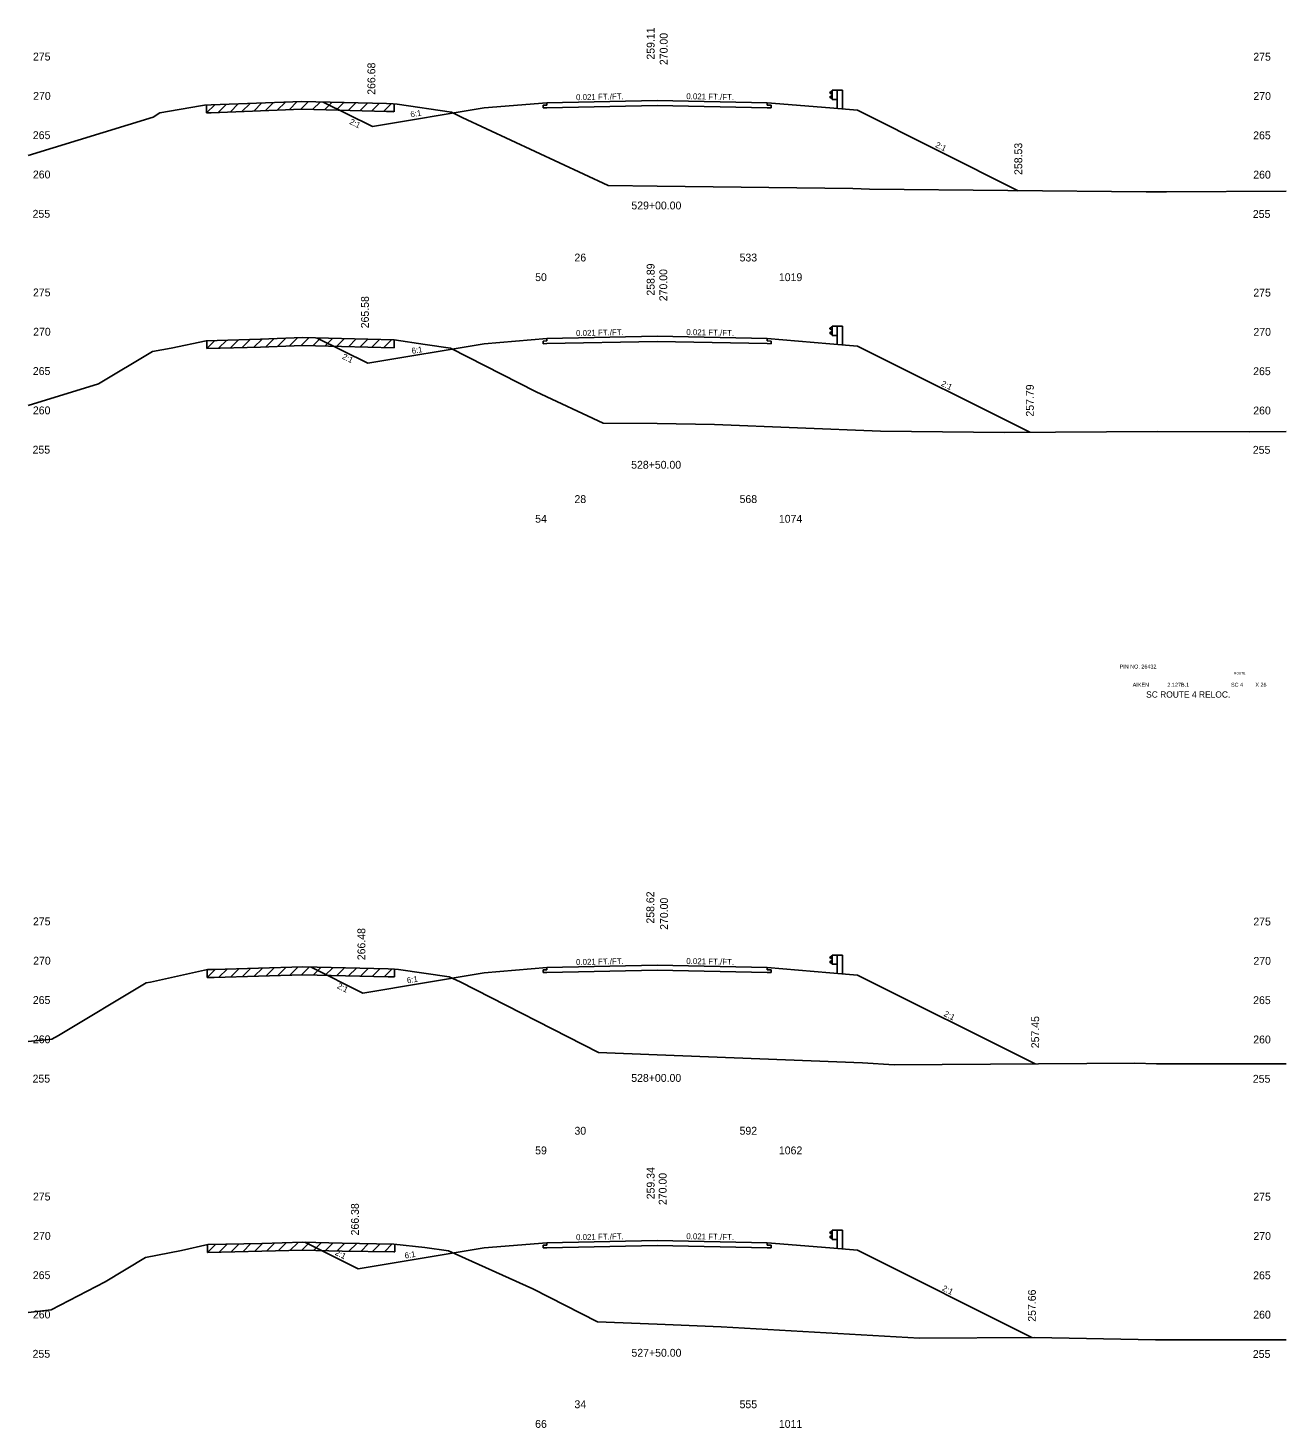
# Model space of a CAD drawing. Extents: x 2967 to 4323, y -3677 to -817.
# Drawn here: x 3555.3 to 3715.3, y -3673.7 to -3495.6 of the extents above; entities that cross this region are included whole.
import ezdxf

# ---------------------------------------------------------------- set-up
doc = ezdxf.new("R2010")
doc.units = 0
for name, color, linetype in [('Level 1', 7, 'Continuous'), ('Level 10', 7, 'Continuous'), ('Level 11', 7, 'Continuous'), ('Level 12', 7, 'Continuous'), ('Level 20', 7, 'Continuous'), ('Level 24', 7, 'Continuous'), ('Level 3', 7, 'Continuous'), ('Level 32', 7, 'Continuous'), ('Level 33', 7, 'Continuous'), ('Level 59', 7, 'Continuous'), ('Level 6', 7, 'Continuous'), ('Level 60', 7, 'Continuous'), ('Level 61', 7, 'Continuous'), ('Level 7', 7, 'Continuous')]:
    doc.layers.add(name, color=color, linetype=linetype)

msp = doc.modelspace()

# ---------------------------------------------------------------- linework, layer by layer
at = {"layer": 'Level 11'}
for p, q in [((3621.35, -3505.43), (3620.85, -3505.44)), ((3620.85, -3505.44), (3620.85, -3505.78)), ((3620.85, -3505.78), (3621.35, -3505.77)), ((3621.35, -3505.13), (3621.35, -3505.43)), ((3649.35, -3505.43), (3649.35, -3505.13)), ((3649.85, -3505.44), (3649.35, -3505.43)), ((3649.35, -3505.77), (3649.85, -3505.78)), ((3649.85, -3505.78), (3649.85, -3505.44)), ((3621.35, -3535.43), (3620.85, -3535.44)), ((3620.85, -3535.44), (3620.85, -3535.78)), ((3620.85, -3535.78), (3621.35, -3535.77)), ((3621.35, -3535.13), (3621.35, -3535.43)), ((3649.35, -3535.43), (3649.35, -3535.13)), ((3649.85, -3535.44), (3649.35, -3535.43)), ((3649.35, -3535.77), (3649.85, -3535.78)), ((3649.85, -3535.78), (3649.85, -3535.44)), ((3621.35, -3615.43), (3620.85, -3615.44)), ((3620.85, -3615.44), (3620.85, -3615.78)), ((3620.85, -3615.78), (3621.35, -3615.77)), ((3621.35, -3615.13), (3621.35, -3615.43)), ((3649.35, -3615.43), (3649.35, -3615.13)), ((3649.85, -3615.44), (3649.35, -3615.43)), ((3649.35, -3615.77), (3649.85, -3615.78)), ((3649.85, -3615.78), (3649.85, -3615.44)), ((3621.35, -3650.43), (3620.85, -3650.44)), ((3620.85, -3650.44), (3620.85, -3650.78)), ((3621.35, -3650.13), (3621.35, -3650.43)), ((3649.35, -3650.43), (3649.35, -3650.13)), ((3649.85, -3650.44), (3649.35, -3650.43)), ((3649.85, -3650.78), (3649.85, -3650.44)), ((3620.85, -3650.78), (3621.35, -3650.77)), ((3649.35, -3650.77), (3649.85, -3650.78))]:
    msp.add_line(p, q, dxfattribs=at)
at = {"layer": 'Level 12'}
for p, q in [((3635.35, -3505.48), (3621.35, -3505.77)), ((3649.35, -3505.77), (3635.35, -3505.48)), ((3635.35, -3535.48), (3621.35, -3535.77)), ((3649.35, -3535.77), (3635.35, -3535.48)), ((3635.35, -3615.48), (3621.35, -3615.77)), ((3649.35, -3615.77), (3635.35, -3615.48)), ((3635.35, -3650.48), (3621.35, -3650.77)), ((3649.35, -3650.77), (3635.35, -3650.48))]:
    msp.add_line(p, q, dxfattribs=at)
at = {"layer": 'Level 24'}
for p, q in [((3657.62, -3503.62), (3657.35, -3503.82)), ((3657.35, -3503.82), (3657.35, -3503.87)), ((3657.35, -3503.87), (3657.62, -3504.07)), ((3657.35, -3504.39), (3657.62, -3504.19)), ((3657.35, -3504.44), (3657.35, -3504.39)), ((3657.62, -3504.64), (3657.35, -3504.44)), ((3657.62, -3504.72), (3657.62, -3503.55)), ((3657.62, -3503.55), (3658.28, -3503.55)), ((3658.28, -3503.55), (3658.28, -3505.88)), ((3658.28, -3503.55), (3658.95, -3503.55)), ((3658.95, -3503.55), (3658.95, -3505.93)), ((3657.62, -3504.72), (3658.29, -3504.72)), ((3657.62, -3533.62), (3657.35, -3533.82)), ((3657.35, -3533.82), (3657.35, -3533.87)), ((3657.35, -3533.87), (3657.62, -3534.07)), ((3657.35, -3534.39), (3657.62, -3534.19)), ((3657.35, -3534.44), (3657.35, -3534.39)), ((3657.62, -3534.64), (3657.35, -3534.44)), ((3657.62, -3534.72), (3657.62, -3533.55)), ((3657.62, -3533.55), (3658.28, -3533.55)), ((3657.62, -3534.72), (3658.29, -3534.72)), ((3658.28, -3533.55), (3658.28, -3535.88)), ((3658.28, -3533.55), (3658.95, -3533.55)), ((3658.95, -3533.55), (3658.95, -3535.93)), ((3657.62, -3613.62), (3657.35, -3613.82)), ((3657.35, -3613.82), (3657.35, -3613.87)), ((3657.35, -3613.87), (3657.62, -3614.07)), ((3657.35, -3614.39), (3657.62, -3614.19)), ((3657.35, -3614.44), (3657.35, -3614.39)), ((3657.62, -3614.64), (3657.35, -3614.44)), ((3657.62, -3614.72), (3657.62, -3613.55)), ((3657.62, -3613.55), (3658.28, -3613.55)), ((3657.62, -3614.72), (3658.29, -3614.72)), ((3658.28, -3613.55), (3658.28, -3615.88)), ((3658.28, -3613.55), (3658.95, -3613.55)), ((3658.95, -3613.55), (3658.95, -3615.93)), ((3657.62, -3648.62), (3657.35, -3648.82)), ((3657.62, -3649.72), (3657.62, -3648.55)), ((3657.62, -3648.55), (3658.28, -3648.55)), ((3658.28, -3648.55), (3658.28, -3650.88)), ((3658.28, -3648.55), (3658.95, -3648.55)), ((3658.95, -3648.55), (3658.95, -3650.93)), ((3657.35, -3648.82), (3657.35, -3648.87)), ((3657.35, -3648.87), (3657.62, -3649.07)), ((3657.35, -3649.39), (3657.62, -3649.19)), ((3657.35, -3649.44), (3657.35, -3649.39)), ((3657.62, -3649.64), (3657.35, -3649.44)), ((3657.62, -3649.72), (3658.29, -3649.72))]:
    msp.add_line(p, q, dxfattribs=at)
at = {"layer": 'Level 59'}
for p, q in [((3621.35, -3505.13), (3635.35, -3504.84)), ((3635.35, -3504.84), (3649.35, -3505.13)), ((3621.35, -3535.13), (3635.35, -3534.84)), ((3635.35, -3534.84), (3649.35, -3535.13)), ((3621.35, -3615.13), (3635.35, -3614.84)), ((3635.35, -3614.84), (3649.35, -3615.13)), ((3621.35, -3650.13), (3635.35, -3649.84)), ((3635.35, -3649.84), (3649.35, -3650.13))]:
    msp.add_line(p, q, dxfattribs=at)
at = {"layer": 'Level 6'}
for p, q in [((3613.35, -3505.8), (3621.35, -3505.13)), ((3649.35, -3505.13), (3657.35, -3505.8)), ((3657.35, -3505.8), (3660.85, -3506.09)), ((3613.35, -3535.8), (3621.35, -3535.13)), ((3649.35, -3535.13), (3657.35, -3535.8)), ((3657.35, -3535.8), (3660.85, -3536.09)), ((3613.35, -3615.8), (3621.35, -3615.13)), ((3649.35, -3615.13), (3657.35, -3615.8)), ((3657.35, -3615.8), (3660.85, -3616.09)), ((3613.35, -3650.8), (3621.35, -3650.13)), ((3649.35, -3650.13), (3657.35, -3650.8)), ((3657.35, -3650.8), (3660.85, -3651.09))]:
    msp.add_line(p, q, dxfattribs=at)
at = {"layer": 'Level 60'}
for p, q in [((3572.12, -3506.43), (3577.27, -3505.54)), ((3577.27, -3505.54), (3577.81, -3505.42)), ((3577.81, -3505.42), (3578.65, -3505.4)), ((3578.65, -3505.4), (3590.18, -3504.97)), ((3590.18, -3504.97), (3600.96, -3505.24)), ((3600.96, -3505.24), (3601.8, -3505.26)), ((3601.8, -3505.26), (3602.29, -3505.33)), ((3602.29, -3505.33), (3609.22, -3506.33)), ((3555.35, -3511.83), (3571.25, -3506.95)), ((3571.25, -3506.95), (3572.12, -3506.43)), ((3609.22, -3506.33), (3610.55, -3507.02)), ((3610.55, -3507.02), (3629.14, -3515.66)), ((3629.14, -3515.66), (3635.35, -3515.73)), ((3635.35, -3515.73), (3660.27, -3516.03)), ((3660.27, -3516.03), (3662.37, -3516.12)), ((3662.37, -3516.12), (3697.56, -3516.48)), ((3697.56, -3516.48), (3699.19, -3516.48)), ((3699.19, -3516.48), (3700.17, -3516.48)), ((3700.17, -3516.48), (3715.35, -3516.4)), ((3571.18, -3536.79), (3573.56, -3536.37)), ((3573.56, -3536.37), (3578, -3535.41)), ((3578, -3535.41), (3584.91, -3535.21)), ((3584.91, -3535.21), (3590.24, -3535.01)), ((3590.24, -3535.01), (3595.21, -3535.14)), ((3595.21, -3535.14), (3601.9, -3535.3)), ((3601.9, -3535.3), (3605.88, -3535.88)), ((3605.88, -3535.88), (3609.07, -3536.34)), ((3609.07, -3536.34), (3620, -3541.92)), ((3564.32, -3540.9), (3571.18, -3536.79)), ((3555.35, -3543.66), (3564.32, -3540.9)), ((3620, -3541.92), (3628.48, -3545.87)), ((3628.48, -3545.87), (3635.35, -3545.95)), ((3635.35, -3545.95), (3642.68, -3546.04)), ((3642.68, -3546.04), (3663.77, -3546.9)), ((3663.77, -3546.9), (3679.53, -3547.07)), ((3679.53, -3547.07), (3699.02, -3546.96)), ((3699.02, -3546.96), (3710.73, -3546.97)), ((3710.73, -3546.97), (3715.35, -3546.94)), ((3570.94, -3616.97), (3578.17, -3615.4)), ((3578.17, -3615.4), (3579.02, -3615.38)), ((3579.02, -3615.38), (3590.29, -3615.05)), ((3590.29, -3615.05), (3601.16, -3615.31)), ((3601.16, -3615.31), (3601.97, -3615.33)), ((3601.97, -3615.33), (3602.46, -3615.38)), ((3602.46, -3615.38), (3608.93, -3616.32)), ((3608.93, -3616.32), (3610.3, -3616.94)), ((3559.22, -3623.77), (3570.37, -3617.08)), ((3570.37, -3617.08), (3570.94, -3616.97)), ((3610.3, -3616.94), (3627.91, -3625.92)), ((3558.37, -3624.22), (3559.22, -3623.77)), ((3555.35, -3624.54), (3558.37, -3624.22)), ((3627.91, -3625.92), (3635.35, -3626.22)), ((3635.35, -3626.22), (3661.5, -3627.27)), ((3661.5, -3627.27), (3665.51, -3627.5)), ((3665.51, -3627.5), (3696.13, -3627.31)), ((3696.13, -3627.31), (3698.86, -3627.36)), ((3698.86, -3627.36), (3715.35, -3627.37)), ((3574.88, -3651.1), (3578.23, -3650.37)), ((3578.23, -3650.37), (3585.09, -3650.22)), ((3585.09, -3650.22), (3590.28, -3650.07)), ((3590.28, -3650.07), (3595.3, -3650.19)), ((3595.3, -3650.19), (3601.86, -3650.3)), ((3601.86, -3650.3), (3605.82, -3650.75)), ((3565.15, -3655.09), (3570.31, -3651.99)), ((3570.31, -3651.99), (3574.88, -3651.1)), ((3605.82, -3650.75), (3608.82, -3651.18)), ((3608.82, -3651.18), (3619.57, -3656)), ((3558.31, -3658.68), (3565.15, -3655.09)), ((3619.57, -3656), (3627.8, -3660.2)), ((3555.35, -3659.01), (3558.31, -3658.68)), ((3627.8, -3660.2), (3635.35, -3660.5)), ((3635.35, -3660.5), (3643.5, -3660.83)), ((3643.5, -3660.83), (3668.74, -3662.27)), ((3668.74, -3662.27), (3683.34, -3662.18)), ((3683.34, -3662.18), (3698.75, -3662.47)), ((3698.75, -3662.47), (3707.37, -3662.47)), ((3707.37, -3662.47), (3715.35, -3662.47))]:
    msp.add_line(p, q, dxfattribs=at)
at = {"layer": 'Level 61'}
for p, q in [((3579.09, -3505.38), (3578.05, -3506.41)), ((3578.05, -3505.41), (3578.05, -3506.41)), ((3578.65, -3506.4), (3590.18, -3505.97)), ((3580.59, -3505.32), (3579.55, -3506.36)), ((3582.09, -3505.27), (3581.05, -3506.31)), ((3583.59, -3505.21), (3582.55, -3506.25)), ((3585.09, -3505.16), (3584.05, -3506.2)), ((3586.59, -3505.1), (3585.55, -3506.14)), ((3588.09, -3505.05), (3587.05, -3506.08)), ((3589.59, -3504.99), (3588.55, -3506.03)), ((3591.04, -3504.99), (3590.05, -3505.97)), ((3590.18, -3505.97), (3600.96, -3506.24)), ((3592.53, -3505.03), (3591.55, -3506)), ((3594.03, -3505.06), (3593.05, -3506.04)), ((3595.53, -3505.1), (3594.55, -3506.08)), ((3597.03, -3505.14), (3596.05, -3506.11)), ((3598.53, -3505.18), (3597.55, -3506.15)), ((3600.03, -3505.21), (3599.05, -3506.19)), ((3601.53, -3505.25), (3600.55, -3506.23)), ((3600.96, -3506.24), (3601.8, -3506.26)), ((3601.9, -3506.27), (3601.9, -3505.27)), ((3578.05, -3506.41), (3578.65, -3506.4)), ((3601.8, -3506.26), (3601.9, -3506.27)), ((3579.12, -3535.38), (3578.09, -3536.41)), ((3578.09, -3535.41), (3578.09, -3536.41)), ((3578.09, -3536.41), (3584.91, -3536.21)), ((3580.62, -3535.33), (3579.59, -3536.36)), ((3582.12, -3535.29), (3581.09, -3536.32)), ((3583.62, -3535.25), (3582.59, -3536.28)), ((3585.12, -3535.2), (3584.09, -3536.23)), ((3584.91, -3536.21), (3590.24, -3536.01)), ((3586.63, -3535.15), (3585.59, -3536.19)), ((3588.13, -3535.09), (3587.09, -3536.13)), ((3589.63, -3535.04), (3588.59, -3536.07)), ((3591.08, -3535.03), (3590.09, -3536.02)), ((3590.24, -3536.01), (3595.21, -3536.14)), ((3592.57, -3535.07), (3591.59, -3536.05)), ((3594.07, -3535.11), (3593.09, -3536.08)), ((3595.57, -3535.15), (3594.59, -3536.12)), ((3595.21, -3536.14), (3601.9, -3536.3)), ((3597.07, -3535.18), (3596.09, -3536.16)), ((3598.57, -3535.22), (3597.59, -3536.19)), ((3600.07, -3535.25), (3599.09, -3536.23)), ((3601.57, -3535.29), (3600.59, -3536.27)), ((3601.9, -3536.3), (3601.94, -3536.3)), ((3601.94, -3536.3), (3601.94, -3535.3)), ((3579.16, -3615.37), (3578.13, -3616.41)), ((3578.13, -3615.41), (3578.13, -3616.41)), ((3578.13, -3616.41), (3578.17, -3616.4)), ((3578.17, -3616.4), (3579.02, -3616.38)), ((3579.02, -3616.38), (3590.29, -3616.05)), ((3580.66, -3615.33), (3579.63, -3616.36)), ((3582.16, -3615.29), (3581.13, -3616.32)), ((3583.66, -3615.25), (3582.63, -3616.27)), ((3585.16, -3615.2), (3584.13, -3616.23)), ((3586.66, -3615.16), (3585.63, -3616.19)), ((3588.16, -3615.12), (3587.13, -3616.15)), ((3589.66, -3615.07), (3588.63, -3616.1)), ((3591.11, -3615.07), (3590.13, -3616.06)), ((3590.29, -3616.05), (3601.16, -3616.31)), ((3592.61, -3615.11), (3591.63, -3616.09)), ((3594.11, -3615.15), (3593.13, -3616.12)), ((3595.61, -3615.18), (3594.63, -3616.16)), ((3597.11, -3615.22), (3596.13, -3616.19)), ((3598.61, -3615.25), (3597.63, -3616.23)), ((3600.11, -3615.29), (3599.13, -3616.27)), ((3601.61, -3615.32), (3600.63, -3616.3)), ((3601.16, -3616.31), (3601.97, -3616.33)), ((3601.97, -3616.33), (3601.98, -3616.33)), ((3601.98, -3616.33), (3601.98, -3615.33)), ((3579.2, -3650.35), (3578.17, -3651.39)), ((3578.17, -3650.39), (3578.17, -3651.39)), ((3580.69, -3650.32), (3579.67, -3651.34)), ((3582.19, -3650.28), (3581.17, -3651.31)), ((3583.69, -3650.25), (3582.67, -3651.27)), ((3585.19, -3650.22), (3584.17, -3651.24)), ((3586.7, -3650.17), (3585.67, -3651.2)), ((3588.2, -3650.13), (3587.17, -3651.16)), ((3589.7, -3650.09), (3588.67, -3651.12)), ((3591.15, -3650.09), (3590.17, -3651.07)), ((3592.64, -3650.13), (3591.67, -3651.1)), ((3594.14, -3650.16), (3593.17, -3651.14)), ((3595.64, -3650.19), (3594.67, -3651.17)), ((3597.15, -3650.22), (3596.17, -3651.2)), ((3598.65, -3650.24), (3597.67, -3651.23)), ((3600.15, -3650.27), (3599.17, -3651.25)), ((3601.65, -3650.29), (3600.67, -3651.28)), ((3602.01, -3651.31), (3602.01, -3650.31)), ((3578.17, -3651.39), (3578.23, -3651.37)), ((3578.23, -3651.37), (3585.09, -3651.22)), ((3585.09, -3651.22), (3590.28, -3651.07)), ((3590.28, -3651.07), (3595.3, -3651.19)), ((3595.3, -3651.19), (3601.86, -3651.3)), ((3601.86, -3651.3), (3602.01, -3651.31))]:
    msp.add_line(p, q, dxfattribs=at)
at = {"layer": 'Level 7'}
for p, q in [((3592.89, -3505.04), (3599.15, -3508.17)), ((3599.15, -3508.17), (3613.35, -3505.8)), ((3660.85, -3506.09), (3681.3, -3516.32)), ((3592.14, -3535.06), (3598.55, -3538.27)), ((3598.55, -3538.27), (3613.35, -3535.8)), ((3660.85, -3536.09), (3682.77, -3547.05)), ((3591.38, -3615.08), (3597.95, -3618.37)), ((3597.95, -3618.37), (3613.35, -3615.8)), ((3660.85, -3616.09), (3683.45, -3627.39)), ((3590.57, -3650.08), (3597.35, -3653.47)), ((3597.35, -3653.47), (3613.35, -3650.8)), ((3660.85, -3651.09), (3683.03, -3662.18))]:
    msp.add_line(p, q, dxfattribs=at)

# ---------------------------------------------------------------- texts
at = {"layer": 'Level 1'}
for s, p in [('26', (3624.85, -3525.32)), ('533', (3645.85, -3525.32)), ('50', (3619.85, -3527.82)), ('1019', (3650.85, -3527.82)), ('28', (3624.85, -3556.05)), ('568', (3645.85, -3556.05)), ('54', (3619.85, -3558.55)), ('1074', (3650.85, -3558.55)), ('30', (3624.85, -3636.39)), ('592', (3645.85, -3636.39)), ('59', (3619.85, -3638.89)), ('1062', (3650.85, -3638.89)), ('34', (3624.85, -3671.18)), ('555', (3645.85, -3671.18)), ('66', (3619.85, -3673.68)), ('1011', (3650.85, -3673.68))]:
    msp.add_text(s, height=1, dxfattribs=at).set_placement(p)
at = {"layer": 'Level 10'}
for s, p in [('259.11', (3635.04, -3499.65)), ('258.89', (3635.04, -3529.67)), ('258.62', (3635, -3609.54)), ('259.34', (3635.04, -3644.61))]:
    msp.add_text(s, height=1, rotation=90, dxfattribs=at).set_placement(p)
for s, p in [('529+00.00', (3632.09, -3518.7)), ('528+50.00', (3632.06, -3551.68)), ('528+00.00', (3632.07, -3629.67)), ('527+50.00', (3632.1, -3664.63))]:
    msp.add_text(s, height=1, dxfattribs=at).set_placement(p)
at = {"layer": 'Level 20'}
for s, height, p in [('PIN NO. 26432', 0.5, (3694.19, -3577.1)), ('AIKEN', 0.5, (3695.85, -3579.41)), (' 2.127B.1', 0.5, (3700.07, -3579.41)), ('SC 4', 0.5, (3708.36, -3579.41)), ('ROUTE', 0.3, (3708.73, -3577.84)), ('X 26', 0.5, (3711.45, -3579.41)), ('SC ROUTE 4 RELOC.', 0.8, (3697.56, -3580.8))]:
    msp.add_text(s, height=height, dxfattribs=at).set_placement(p)
at = {"layer": 'Level 3'}
for s, p in [(' 275', (3555.61, -3499.76)), (' 275', (3710.82, -3499.78)), (' 270', (3555.63, -3504.76)), (' 270', (3710.83, -3504.78)), (' 265', (3555.59, -3509.76)), (' 265', (3710.8, -3509.78)), (' 260', (3555.6, -3514.76)), (' 260', (3710.81, -3514.78)), (' 255', (3555.56, -3519.76)), (' 255', (3710.76, -3519.78)), (' 275', (3555.61, -3529.76)), (' 275', (3710.82, -3529.78)), (' 270', (3555.63, -3534.76)), (' 270', (3710.83, -3534.78)), (' 265', (3555.59, -3539.76)), (' 265', (3710.8, -3539.78)), (' 260', (3555.6, -3544.76)), (' 260', (3710.81, -3544.78)), (' 255', (3555.56, -3549.76)), (' 255', (3710.76, -3549.78)), (' 275', (3555.61, -3609.76)), (' 275', (3710.82, -3609.78)), (' 270', (3555.63, -3614.76)), (' 270', (3710.83, -3614.78)), (' 265', (3555.59, -3619.76)), (' 265', (3710.8, -3619.78)), (' 260', (3555.6, -3624.76)), (' 260', (3710.81, -3624.78)), (' 255', (3555.56, -3629.76)), (' 255', (3710.76, -3629.78)), (' 275', (3555.61, -3644.76)), (' 275', (3710.82, -3644.78)), (' 270', (3555.63, -3649.76)), (' 270', (3710.83, -3649.78)), (' 265', (3555.59, -3654.76)), (' 265', (3710.8, -3654.78)), (' 260', (3555.6, -3659.76)), (' 260', (3710.81, -3659.78)), (' 255', (3555.56, -3664.76)), (' 255', (3710.76, -3664.78))]:
    msp.add_text(s, height=1, dxfattribs=at).set_placement(p)
at = {"layer": 'Level 32'}
for s, rotation, p in [('0.021 FT./FT.', 1.1916, (3625.06, -3504.81)), ('0.021 FT./FT.', 358.8084, (3639.07, -3504.67)), ('6:1', 9.4623, (3604.05, -3507)), ('2:1', 333.435, (3596.16, -3507.79)), ('2:1', 333.435, (3670.68, -3510.73)), ('0.021 FT./FT.', 1.1916, (3625.06, -3534.81)), ('0.021 FT./FT.', 358.8084, (3639.07, -3534.67)), ('6:1', 9.4623, (3604.2, -3537.07)), ('2:1', 333.435, (3595.23, -3537.66)), ('2:1', 333.435, (3671.41, -3541.09)), ('0.021 FT./FT.', 1.1916, (3625.06, -3614.81)), ('0.021 FT./FT.', 358.8084, (3639.07, -3614.67)), ('6:1', 9.4623, (3603.6, -3617.15)), ('2:1', 333.435, (3594.59, -3617.72)), ('2:1', 333.435, (3671.75, -3621.26)), ('0.021 FT./FT.', 1.1916, (3625.06, -3649.81)), ('0.021 FT./FT.', 358.8084, (3639.07, -3649.67)), ('2:1', 333.435, (3594.32, -3651.63)), ('6:1', 9.4623, (3603.31, -3652.15)), ('2:1', 333.435, (3671.54, -3656.16))]:
    msp.add_text(s, height=0.75, rotation=rotation, dxfattribs=at).set_placement(p)
at = {"layer": 'Level 33'}
for s, p in [('266.68', (3599.52, -3504.12)), ('258.53', (3681.8, -3514.32)), ('265.58', (3598.7, -3533.82)), ('257.79', (3683.27, -3545.05)), ('266.48', (3598.25, -3614.2)), ('257.45', (3683.95, -3625.39)), ('266.38', (3597.43, -3649.2)), ('257.66', (3683.53, -3660.18))]:
    msp.add_text(s, height=1, rotation=90, dxfattribs=at).set_placement(p)
at = {"layer": 'Level 59'}
for p in [(3636.7, -3500.71), (3636.65, -3530.75), (3636.74, -3610.71), (3636.57, -3645.71)]:
    msp.add_text(' 270.00', height=1, rotation=90, dxfattribs=at).set_placement(p)

doc.saveas('drawing.dxf')
